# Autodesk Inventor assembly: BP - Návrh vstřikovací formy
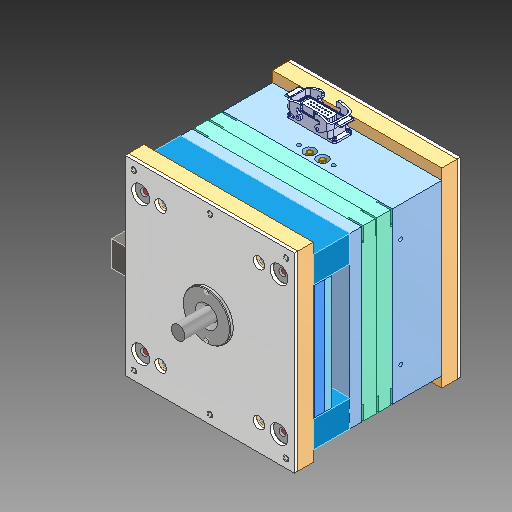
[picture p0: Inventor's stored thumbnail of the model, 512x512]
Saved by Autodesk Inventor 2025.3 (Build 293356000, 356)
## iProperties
Company: Univerzita
Created: 2025-02
Part Number: BP - Návrh vstřikovací formy
Document SubType Name: Assembly
Designer: Patrik
Author: Kadlčík Patrik
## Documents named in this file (50)
- C:\Users\Patrik\Documents\Skola\Bakalarska prace\Prakticka cast\Sestava - mold design.iam
- C:\Users\Patrik\Documents\Skola\Bakalarska prace\Prakticka cast\Sestava - mold design_MODEL - mk4 Blenddoor Tab v4_2_LY.iam
- C:\Users\Patrik\Documents\Skola\Bakalarska prace\Prakticka cast\MODEL - mk4 Blenddoor Tab v4_2.ipt
- C:\Users\Patrik\Documents\Skola\Bakalarska prace\Prakticka cast\E 31621_52_30_63.iam
- C:\Users\Patrik\Documents\Skola\Bakalarska prace\Prakticka cast\Z70_3.iam
- C:\Users\Patrik\Documents\Skola\Bakalarska prace\Prakticka cast\E 2071_9.ipt
- C:\Users\Patrik\Documents\Skola\Bakalarska prace\Prakticka cast\E 2071_9_1.ipt
- C:\Users\Patrik\Documents\Skola\Bakalarska prace\Prakticka cast\E 2071_9_2.ipt
- C:\Users\Patrik\Documents\Skola\Bakalarska prace\Prakticka cast\E 2071_9_3.ipt
- C:\Users\Patrik\Documents\Skola\Bakalarska prace\Prakticka cast\E 2071_9_4.ipt
- C:\Users\Patrik\Documents\Skola\Bakalarska prace\Prakticka cast\E 2071_9_7.ipt
- C:\Users\Patrik\Documents\Skola\Bakalarska prace\Prakticka cast\E 2071_9_11.ipt
- C:\Users\Patrik\Documents\Skola\Bakalarska prace\Prakticka cast\E 2071_9_15.ipt
- C:\Users\Patrik\Documents\Skola\Bakalarska prace\Prakticka cast\E 2071_9_19.ipt
- C:\Users\Patrik\Documents\Skola\Bakalarska prace\Prakticka cast\E 2071_9_20.ipt
- C:\Users\Patrik\Documents\Skola\Bakalarska prace\Prakticka cast\E 2071_9_21.ipt
- C:\Users\Patrik\Documents\Skola\Bakalarska prace\Prakticka cast\E 2071_9_22.ipt
- C:\Users\Patrik\Documents\Skola\Bakalarska prace\Prakticka cast\E 2071_9_23.ipt
- C:\Users\Patrik\Documents\Skola\Bakalarska prace\Prakticka cast\E 2071_9_24.ipt
- C:\Users\Patrik\Documents\Skola\Bakalarska prace\Prakticka cast\E 2071_9_25.ipt
- C:\Users\Patrik\Documents\Skola\Bakalarska prace\Prakticka cast\E 2071_9_26.ipt
- C:\Users\Patrik\Documents\Skola\Bakalarska prace\Prakticka cast\E 2071_9_27.ipt
- C:\Users\Patrik\Documents\Skola\Bakalarska prace\Prakticka cast\E 2071_9_28.ipt
- C:\Users\Patrik\Documents\Skola\Bakalarska prace\Prakticka cast\E 2071_9_29.ipt
- C:\Users\Patrik\Documents\Skola\Bakalarska prace\Prakticka cast\E 2071_9_33.ipt
- C:\Users\Patrik\Documents\Skola\Bakalarska prace\Prakticka cast\E 2071_9_37.ipt
- C:\Users\Patrik\Documents\Skola\Bakalarska prace\Prakticka cast\E 2071_9_41.ipt
- C:\Users\Patrik\Documents\Skola\Bakalarska prace\Prakticka cast\E 2071_9_45.ipt
- C:\Users\Patrik\Documents\Skola\Bakalarska prace\Prakticka cast\E 2071_9_46.ipt
- C:\Users\Patrik\Documents\Skola\Bakalarska prace\Prakticka cast\Temperacni system.iam
- C:\Users\Patrik\Documents\Skola\Bakalarska prace\Prakticka cast\E 1770 DLC_2x160.ipt
- C:\Users\Patrik\Documents\Skola\Bakalarska prace\Prakticka cast\E 1220_6x12.ipt
- C:\Users\Patrik\Documents\Skola\Bakalarska prace\Prakticka cast\E 1362_110_90_30x12.ipt
- C:\Users\Patrik\Documents\Skola\Bakalarska prace\Prakticka cast\E 1200_6x12.ipt
- C:\Users\Patrik\Documents\Skola\Bakalarska prace\Prakticka cast\E 2071_9_5.ipt
- C:\Users\Patrik\Documents\Skola\Bakalarska prace\Prakticka cast\E 2071_9_6.ipt
- C:\Users\Patrik\Documents\Skola\Bakalarska prace\Prakticka cast\E 1928_32_120.ipt
- C:\Users\Patrik\Documents\Skola\Bakalarska prace\Prakticka cast\E 2710_16B.iam
- C:\Users\Patrik\Documents\Skola\Bakalarska prace\Prakticka cast\E 3014_16_20.ipt
- C:\Users\Patrik\Documents\Skola\Bakalarska prace\Prakticka cast\E 1200_6x16.ipt
- C:\Users\Patrik\Documents\Skola\Bakalarska prace\Prakticka cast\E 2071_9_75.ipt
- C:\Users\Patrik\Documents\Skola\Bakalarska prace\Prakticka cast\E 1034_10x70.ipt
- C:\Users\Patrik\Documents\Skola\Bakalarska prace\Prakticka cast\E 1034_10x70_MIR.ipt
- C:\Users\Patrik\Documents\Skola\Bakalarska prace\Prakticka cast\E 1200_6x16_MIR.ipt
- C:\Users\Patrik\Documents\Skola\Bakalarska prace\Prakticka cast\E 31621_52_30_63_MIR.iam
- C:\Users\Patrik\Documents\Skola\Bakalarska prace\Prakticka cast\E 3014_16_20_MIR.ipt
- C:\Users\Patrik\Documents\Skola\Bakalarska prace\Prakticka cast\E 1200_4x10.ipt
- C:\Users\Patrik\Documents\Skola\Bakalarska prace\Prakticka cast\E 2071_9_74.ipt
- C:\Users\Patrik\Documents\Skola\Bakalarska prace\Prakticka cast\E 1034_14x110.ipt
- C:\Users\Patrik\Documents\Skola\Bakalarska prace\Prakticka cast\E 1120_14-17_22.ipt
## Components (115 placed, 72 different names)
1. S01-00 - Tvárník / Tvárnice [sub-assembly]
2. S02-01 - Deska izolační pravá — Vložit:59, Vložit:60
3. S02-02 - Deska opěrná pravá — Proti sobě:46
4. S02-03 - Deska horkého vtoku
5. S02-04 - Deska tvarová pravá — Stejný směr:7, Proti sobě:14
6. S02-05 - Deska tvarová levá — Proti sobě:14, Proti sobě:25, Proti sobě:26
7. S02-06 - Deska opěrná levá
8. S02-07 - Deska rozpěrná
9. S02-08 - Deska opěrná levá
10. S02-09 - Deska izolační levá — Vložit:76, Vložit:80
11. S02-11 - E 1002 DLC/30-36/55 - Kolík 1
12. S02-12 - E 1002 DLC/32-36/55 - Kolík 2
13. S02-12 - E 1002 DLC/32-36/55 - Kolík 3
14. S02-12 - E 1002 DLC/32-36/55 - Kolík 4
15. S02-14 - E 1105/30-36 - Pouzdro 1
16. S02-14 - E 1105/32-36 - Pouzdro 2
17. S02-14 - E 1105/32-36 - Pouzdro 3
18. S02-14 - E 1105/32-36 - Pouzdro 4
19. S02-19 - Středící kroužek Pravý — Vložit:60, Vložit:61, Proti sobě:36
20. S02-19 - Středící kroužek Levý — Vložit:76, Proti sobě:36, Vložit:79
21. S03-01 - Vyhazovací deska — Vložit:81, Vložit:82
22. S03-02 - Vyhazovaci deska opěrná
23. S03-08 - Ovládací táhlo — Proti sobě:22, Stejný směr:24
24. S05-01 - Temperacni system [sub-assembly] — Vložit:55, Proti sobě:11, Stejný směr:25, Stejný směr:26
25. S05-02 - E 2000 D - Přípojka 1
26. S05-02 - E 2000 D - Přípojka 2
27. S05-03 - E 2071/ 9 - Kuličková záslepka 1 — Proti sobě:37, Proti sobě:38
28. S05-03 - E 2071/ 9 - Kuličková záslepka 2 — Proti sobě:39, Proti sobě:40
29. S05-03 - E 2071/ 9 - Kuličková záslepka 3 — Proti sobě:41, Proti sobě:42
30. S05-03 - E 2071/ 9 - Kuličková záslepka 4 — Proti sobě:43
31. S05-03 - E 2071/ 9 - Kuličková záslepka 5 — Proti sobě:44
32. S06-01 - Elektrická přípojka [sub-assembly] — Proti sobě:24, Stejný směr:25, Stejný směr:26, Proti sobě:45, Proti sobě:46, Proti sobě:50, Stejný směr:39, Stejný směr:40, Stejný směr:41, Stejný směr:42
33. S07-01 - Z70_3 - Transport [sub-assembly] — Tečnost:9, Proti sobě:21, Stejný směr:37
34. MODEL - mk4 Blenddoor Tab v4_2:1 — Proti sobě:8, Proti sobě:9, Proti sobě:10, Proti sobě:11
35. MODEL - mk4 Blenddoor Tab v4_2:2
36. S01-10 - E 1160/42 x 40 - Pouzdro 1
37. E 2071_9_33:2
38. E 2071_9_33:3
39. E 2071_9_33:4
40. S01-15 - E 1160/42x140 - Pouzdro 1 — Vložit:22
41. E 2071_9_29:2
42. E 2071_9_29:3
43. E 2071_9_29:4
44. S01-16 - E 1200/16 x160 - Šroub 1
45. E 2071_9_37:2
46. E 2071_9_37:3
47. E 2071_9_37:4
48. S01-17 - E 1200/16 x150 - Šroub 1
49. E 2071_9_41:2
50. E 2071_9_41:3
51. E 2071_9_41:4
52. E 1220_6x12:7 — Vložit:59
53. E 1220_6x12:8
54. E 1220_6x12:9
55. E 1220_6x12:10
56. E 1220_6x12:11
57. E 1220_6x12:12
58. S01-24 - ŠROUB - IZOLAČNÍ — Vložit:80
59. E 1220_6x12:2
60. E 1220_6x12:3
61. E 1220_6x12:4
62. E 1220_6x12:5
63. E 1220_6x12:6
64. E 1200_6x12:1 ŠROUB — Vložit:61
65. E 1200_6x12:2
66. E 1200_6x12:3 — Vložit:79
67. E 1200_6x12:4
68. S03-03 - Dosedka 1 — Vložit:83, Proti sobě:49
69. E 2071_9_7:2
70. E 2071_9_7:3
71. E 2071_9_7:4
72. S03-04 - Dosedka - Šroub
73. E 2071_9_11:2
74. E 2071_9_11:3
75. E 2071_9_11:4
76. S03-05 - Vyhazovací paket - Šroub 1
77. E 2071_9_15:2
78. E 2071_9_15:3
79. E 2071_9_15:4
80. E 1200_6x16_MIR:3 — Vložit:84
81. E 1034_14x110:1 — Proti sobě:47, Proti sobě:48, Tečnost:10, Tečnost:11
82. E 1120_14-17_22:1 — Proti sobě:47, Stejný směr:38
83. E 1200_6x16_MIR:4
84. E 1034_14x110:2
85. E 1120_14-17_22:2
86. E 1200_6x16_MIR:5
87. E 1034_14x110:3
88. E 1120_14-17_22:3
89. E 1200_6x16_MIR:6
90. E 1034_14x110:4
91. E 1120_14-17_22:4
92. Vyhazovač 2
93. Vyhazovač 1
94. E 1770 DLC_2x160:3
95. E 1770 DLC_2x160:4
96. S02-01-E 31621_52_30 - Mechanizmus MIR [sub-assembly] — Vložit:71, Vložit:72
97. S02-01-E 31621_52_30 - Mechanizmus [sub-assembly] — Proti sobě:20, Proti sobě:33
98. S02-02-E 3014_16-Tvarová vložka - vedlejší — Proti sobě:30
99. S02-02-E 3014_16-Tvarová vložka - vedlejší MIR — Vložit:71, Vložit:72, Vložit:78
100. E 1200_4x10:1
101. E 1200_4x10:2 — Vložit:78
102. E 31621_52_30_63_MIR:2 [sub-assembly]
103. E 31621_52_30_63:2 [sub-assembly]
104. E 3014_16_20:2
105. E 3014_16_20_MIR:2
106. E 1200_4x10:3
107. E 1200_4x10:4
108. S02-03 - E 1200_6x16:1 - Imbusový šroub s válcovou hlavou
109. S02-03 - E 1034_10x60 - Šikmý kolík bez nákružku — Proti sobě:33
110. E 1034_10x70_MIR:1 — Proti sobě:34, Proti sobě:35
111. E 1200_6x16_MIR:1 — Proti sobě:34, Proti sobě:35
112. E 1200_6x16:2
113. E 1034_10x70:2
114. E 1034_10x70_MIR:2
115. E 1200_6x16_MIR:2
## Component patterns: S00-00 - Model (2 elements), S02-10 - Pouzdro (4 elements), S02-15 - E 1160/42x140 - Pouzdro (4 elements), S02-16 - Šrouby 16x160 (4 elements), S02-17 - Šrouby 16x150 (4 elements), S02-18 - ŠROUBY - IZOLAČNÍ PRAVÁ (6 elements), S02-18 - ŠROUBY - IZOLAČNÍ LEVÁ (6 elements), S02-20 - Šrouby - Středící kroužek Pravý (2 elements), S02-20 - Šrouby - Středící kroužek Levý (2 elements), S03-03 - Dosedka (4 elements), S03-04 - Dosedka - šroub (4 elements), S03-05 - Vyhazovaci paket - šrouby (4 elements), S03-06 - Vyhazovaci paket - čepy (4 elements), S03-07 - Vyhazovače (2 elements), S04-01/2/3 - ŠÍBR (2 elements), S04-04/5 - ŠÍBR - Vodící Kolíky (2 elements)
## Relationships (58: Mate 30, Insert 15, Flush 10, Tangent 3)
- Vložit:22 [Insert]: S01-15 - E 1160/42x140 - Pouzdro 1
- Vložit:55 [Insert]: S05-01 - Temperacni system
- Stejný směr:7 [Flush]: S02-04 - Deska tvarová pravá
- Proti sobě:8 [Mate]: MODEL - mk4 Blenddoor Tab v4_2:1
- Proti sobě:9 [Mate]: MODEL - mk4 Blenddoor Tab v4_2:1
- Proti sobě:10 [Mate]: MODEL - mk4 Blenddoor Tab v4_2:1
- Proti sobě:11 [Mate]: S05-01 - Temperacni system ↔ MODEL - mk4 Blenddoor Tab v4_2:1
- Proti sobě:14 [Mate]: S02-04 - Deska tvarová pravá ↔ S02-05 - Deska tvarová levá
- Proti sobě:20 [Mate]: S02-01-E 31621_52_30 - Mechanizmus
- Vložit:59 [Insert]: S02-01 - Deska izolační pravá ↔ E 1220_6x12:7
- Vložit:60 [Insert]: S02-01 - Deska izolační pravá ↔ S02-19 - Středící kroužek Pravý
- Vložit:61 [Insert]: S02-19 - Středící kroužek Pravý ↔ E 1200_6x12:1 ŠROUB
- Tečnost:9 [Tangent]: S07-01 - Z70_3 - Transport
- Proti sobě:21 [Mate]: S07-01 - Z70_3 - Transport
- Stejný směr:37 [Flush]: S07-01 - Z70_3 - Transport
- Proti sobě:22 [Mate]: S03-08 - Ovládací táhlo
- Stejný směr:24 [Flush]: S03-08 - Ovládací táhlo
- Proti sobě:24 [Mate]: S06-01 - Elektrická přípojka
- Proti sobě:25 [Mate]: S02-05 - Deska tvarová levá
- Proti sobě:26 [Mate]: S02-05 - Deska tvarová levá
- Proti sobě:30 [Mate]: S02-02-E 3014_16-Tvarová vložka - vedlejší
- Proti sobě:33 [Mate]: S02-01-E 31621_52_30 - Mechanizmus ↔ S02-03 - E 1034_10x60 - Šikmý kolík bez nákružku
- Proti sobě:34 [Mate]: E 1034_10x70_MIR:1 ↔ E 1200_6x16_MIR:1
- Proti sobě:35 [Mate]: E 1034_10x70_MIR:1 ↔ E 1200_6x16_MIR:1
- Vložit:71 [Insert]: S02-01-E 31621_52_30 - Mechanizmus MIR ↔ S02-02-E 3014_16-Tvarová vložka - vedlejší MIR
- Vložit:72 [Insert]: S02-01-E 31621_52_30 - Mechanizmus MIR ↔ S02-02-E 3014_16-Tvarová vložka - vedlejší MIR
- Stejný směr:25 [Flush]: S05-01 - Temperacni system ↔ S06-01 - Elektrická přípojka
- Stejný směr:26 [Flush]: S05-01 - Temperacni system ↔ S06-01 - Elektrická přípojka
- Vložit:76 [Insert]: S02-09 - Deska izolační levá ↔ S02-19 - Středící kroužek Levý
- Proti sobě:36 [Mate]: S02-19 - Středící kroužek Pravý ↔ S02-19 - Středící kroužek Levý
- Vložit:78 [Insert]: S02-02-E 3014_16-Tvarová vložka - vedlejší MIR ↔ E 1200_4x10:2
- Vložit:79 [Insert]: S02-19 - Středící kroužek Levý ↔ E 1200_6x12:3
- Vložit:80 [Insert]: S02-09 - Deska izolační levá ↔ S01-24 - ŠROUB - IZOLAČNÍ
- Proti sobě:37 [Mate]: S05-03 - E 2071/ 9 - Kuličková záslepka 1
- Proti sobě:38 [Mate]: S05-03 - E 2071/ 9 - Kuličková záslepka 1
- Proti sobě:39 [Mate]: S05-03 - E 2071/ 9 - Kuličková záslepka 2
- Proti sobě:40 [Mate]: S05-03 - E 2071/ 9 - Kuličková záslepka 2
- Proti sobě:41 [Mate]: S05-03 - E 2071/ 9 - Kuličková záslepka 3
- Proti sobě:42 [Mate]: S05-03 - E 2071/ 9 - Kuličková záslepka 3
- Proti sobě:43 [Mate]: S05-03 - E 2071/ 9 - Kuličková záslepka 4
- Proti sobě:44 [Mate]: S05-03 - E 2071/ 9 - Kuličková záslepka 5
- Proti sobě:45 [Mate]: S06-01 - Elektrická přípojka
- Proti sobě:46 [Mate]: S02-02 - Deska opěrná pravá ↔ S06-01 - Elektrická přípojka
- Vložit:81 [Insert]: S03-01 - Vyhazovací deska
- Proti sobě:47 [Mate]: E 1034_14x110:1 ↔ E 1120_14-17_22:1
- Proti sobě:48 [Mate]: E 1034_14x110:1
- Stejný směr:38 [Flush]: E 1120_14-17_22:1
- Tečnost:10 [Tangent]: E 1034_14x110:1
- Tečnost:11 [Tangent]: E 1034_14x110:1
- Vložit:82 [Insert]: S03-01 - Vyhazovací deska
- Vložit:83 [Insert]: S03-03 - Dosedka 1
- Proti sobě:49 [Mate]: S03-03 - Dosedka 1
- Vložit:84 [Insert]: E 1200_6x16_MIR:3
- Proti sobě:50 [Mate]: S06-01 - Elektrická přípojka
- Stejný směr:39 [Flush]: S06-01 - Elektrická přípojka
- Stejný směr:40 [Flush]: S06-01 - Elektrická přípojka
- Stejný směr:41 [Flush]: S06-01 - Elektrická přípojka
- Stejný směr:42 [Flush]: S06-01 - Elektrická přípojka
## Named parameters: d249_d111 = 0, d423_d36 = 0, d427_d0 = 0, d428_d1 = 0
